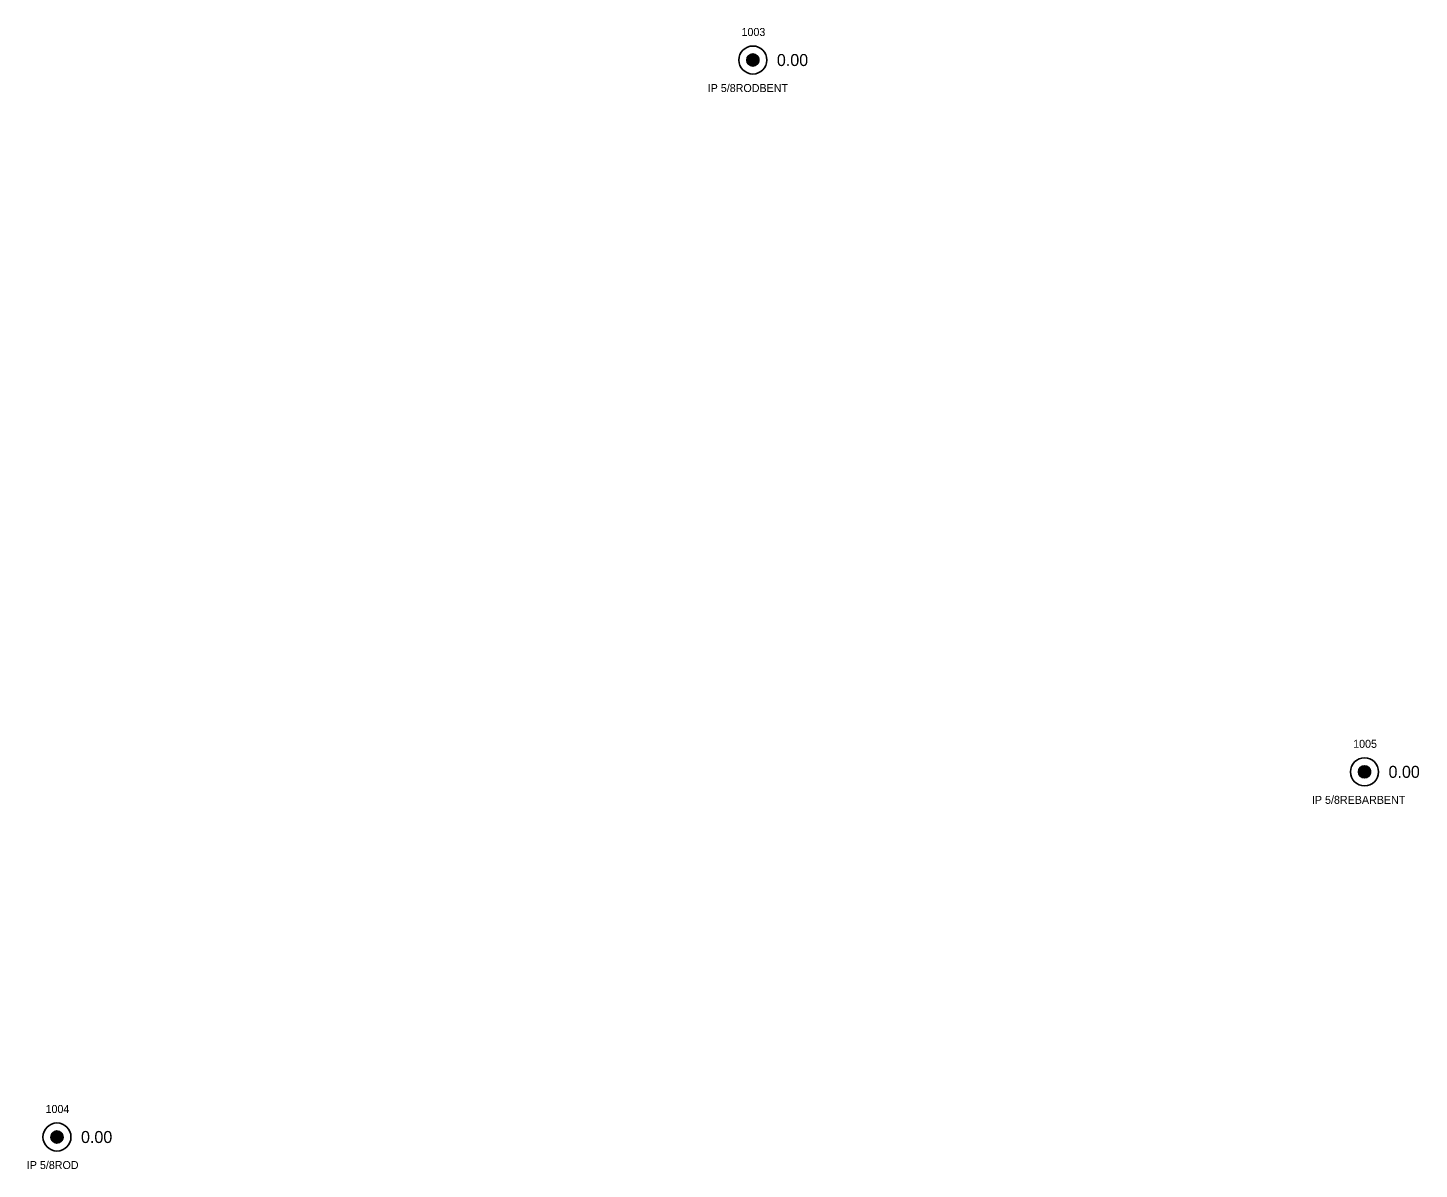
# Model space of a CAD drawing. Extents: x 2139392 to 2143384, y 505395 to 510520.
# Drawn here: x 2140586.9 to 2140760.7, y 505394.8 to 505537.4 of the extents above; entities that cross this region are included whole.
import ezdxf

# ---------------------------------------------------------------- set-up
doc = ezdxf.new("R2010")
doc.units = 0
for name, color, linetype in [('RD_EX_DV_Prop_txCode', 7, 'Continuous'), ('RD_EX_DV_PropPin', 7, 'Continuous'), ('RD_EX_TX_DV_Prop_ELEV', 7, 'Continuous'), ('RD_SMD_Locator', 7, 'Continuous')]:
    doc.layers.add(name, color=color, linetype=linetype)

msp = doc.modelspace()

# ---------------------------------------------------------------- linework, layer by layer
at = {"layer": 'RD_EX_DV_PropPin'}
for p, q in [((2140676.75, 505533.18), (2140676.75, 505533.57)), ((2140676.78, 505533.08), (2140676.78, 505533.67)), ((2140676.82, 505533.01), (2140676.82, 505533.74)), ((2140676.85, 505532.95), (2140676.85, 505533.8)), ((2140676.89, 505532.9), (2140676.89, 505533.85)), ((2140676.92, 505532.86), (2140676.92, 505533.89)), ((2140676.96, 505532.82), (2140676.96, 505533.93)), ((2140676.99, 505532.79), (2140676.99, 505533.96)), ((2140677.03, 505532.76), (2140677.03, 505533.98)), ((2140677.06, 505532.74), (2140677.06, 505534.01)), ((2140677.1, 505532.72), (2140677.1, 505534.03)), ((2140677.13, 505532.7), (2140677.13, 505534.05)), ((2140677.17, 505532.68), (2140677.17, 505534.07)), ((2140677.2, 505532.67), (2140677.2, 505534.08)), ((2140677.24, 505532.65), (2140677.24, 505534.1)), ((2140677.27, 505532.64), (2140677.27, 505534.11)), ((2140677.31, 505532.63), (2140677.31, 505534.12)), ((2140677.34, 505532.63), (2140677.34, 505534.12)), ((2140677.38, 505532.62), (2140677.38, 505534.13)), ((2140677.41, 505532.62), (2140677.41, 505534.13)), ((2140677.45, 505532.61), (2140677.45, 505534.14)), ((2140677.48, 505532.61), (2140677.48, 505534.14)), ((2140677.52, 505532.61), (2140677.52, 505534.14)), ((2140677.55, 505532.62), (2140677.55, 505534.13)), ((2140677.59, 505532.62), (2140677.59, 505534.13)), ((2140677.62, 505532.63), (2140677.62, 505534.12)), ((2140677.66, 505532.63), (2140677.66, 505534.12)), ((2140677.69, 505532.64), (2140677.69, 505534.11)), ((2140677.73, 505532.65), (2140677.73, 505534.1)), ((2140677.76, 505532.67), (2140677.76, 505534.08)), ((2140677.8, 505532.68), (2140677.8, 505534.07)), ((2140677.83, 505532.7), (2140677.83, 505534.05)), ((2140677.87, 505532.72), (2140677.87, 505534.03)), ((2140677.9, 505532.74), (2140677.9, 505534.01)), ((2140677.94, 505532.76), (2140677.94, 505533.98)), ((2140677.97, 505532.79), (2140677.97, 505533.96)), ((2140678.01, 505532.82), (2140678.01, 505533.93)), ((2140678.04, 505532.86), (2140678.04, 505533.89)), ((2140678.08, 505532.9), (2140678.08, 505533.85)), ((2140678.11, 505532.95), (2140678.11, 505533.8)), ((2140678.15, 505533.01), (2140678.15, 505533.74)), ((2140678.18, 505533.08), (2140678.18, 505533.67)), ((2140678.22, 505533.18), (2140678.22, 505533.57)), ((2140753.16, 505444.27), (2140753.16, 505444.66)), ((2140753.19, 505444.16), (2140753.19, 505444.76)), ((2140753.23, 505444.09), (2140753.23, 505444.83)), ((2140753.26, 505444.04), (2140753.26, 505444.89)), ((2140753.3, 505443.99), (2140753.3, 505444.94)), ((2140753.33, 505443.95), (2140753.33, 505444.98)), ((2140753.37, 505443.91), (2140753.37, 505445.01)), ((2140753.4, 505443.88), (2140753.4, 505445.04)), ((2140753.44, 505443.85), (2140753.44, 505445.07)), ((2140753.47, 505443.83), (2140753.47, 505445.1)), ((2140753.51, 505443.81), (2140753.51, 505445.12)), ((2140753.54, 505443.79), (2140753.54, 505445.14)), ((2140753.58, 505443.77), (2140753.58, 505445.15)), ((2140753.61, 505443.75), (2140753.61, 505445.17)), ((2140753.65, 505443.74), (2140753.65, 505445.18)), ((2140753.68, 505443.73), (2140753.68, 505445.19)), ((2140753.72, 505443.72), (2140753.72, 505445.2)), ((2140753.75, 505443.71), (2140753.75, 505445.21)), ((2140753.79, 505443.71), (2140753.79, 505445.22)), ((2140753.82, 505443.7), (2140753.82, 505445.22)), ((2140753.86, 505443.7), (2140753.86, 505445.22)), ((2140753.89, 505443.7), (2140753.89, 505445.22)), ((2140753.93, 505443.7), (2140753.93, 505445.22)), ((2140753.96, 505443.7), (2140753.96, 505445.22)), ((2140754, 505443.71), (2140754, 505445.22)), ((2140754.03, 505443.71), (2140754.03, 505445.21)), ((2140754.07, 505443.72), (2140754.07, 505445.2)), ((2140754.1, 505443.73), (2140754.1, 505445.19)), ((2140754.14, 505443.74), (2140754.14, 505445.18)), ((2140754.17, 505443.75), (2140754.17, 505445.17)), ((2140754.21, 505443.77), (2140754.21, 505445.15)), ((2140754.24, 505443.79), (2140754.24, 505445.14)), ((2140754.28, 505443.81), (2140754.28, 505445.12)), ((2140754.31, 505443.83), (2140754.31, 505445.1)), ((2140754.35, 505443.85), (2140754.35, 505445.07)), ((2140754.38, 505443.88), (2140754.38, 505445.04)), ((2140754.42, 505443.91), (2140754.42, 505445.01)), ((2140754.45, 505443.95), (2140754.45, 505444.98)), ((2140754.49, 505443.99), (2140754.49, 505444.94)), ((2140754.52, 505444.04), (2140754.52, 505444.89)), ((2140754.56, 505444.09), (2140754.56, 505444.83)), ((2140754.59, 505444.16), (2140754.59, 505444.76)), ((2140754.63, 505444.27), (2140754.63, 505444.66)), ((2140589.88, 505398.48), (2140589.88, 505399.22)), ((2140589.92, 505398.42), (2140589.92, 505399.27)), ((2140589.95, 505398.37), (2140589.95, 505399.32)), ((2140589.99, 505398.33), (2140589.99, 505399.36)), ((2140590.02, 505398.3), (2140590.02, 505399.4)), ((2140590.06, 505398.27), (2140590.06, 505399.43)), ((2140590.09, 505398.24), (2140590.09, 505399.46)), ((2140590.13, 505398.21), (2140590.13, 505399.48)), ((2140590.16, 505398.19), (2140590.16, 505399.5)), ((2140590.2, 505398.17), (2140590.2, 505399.52)), ((2140590.23, 505398.15), (2140590.23, 505399.54)), ((2140590.27, 505398.14), (2140590.27, 505399.55)), ((2140590.3, 505398.13), (2140590.3, 505399.57)), ((2140590.34, 505398.12), (2140590.34, 505399.58)), ((2140590.37, 505398.11), (2140590.37, 505399.59)), ((2140590.41, 505398.1), (2140590.41, 505399.6)), ((2140590.44, 505398.09), (2140590.44, 505399.6)), ((2140590.48, 505398.09), (2140590.48, 505399.6)), ((2140590.51, 505398.09), (2140590.51, 505399.61)), ((2140590.55, 505398.09), (2140590.55, 505399.61)), ((2140590.58, 505398.09), (2140590.58, 505399.61)), ((2140590.62, 505398.09), (2140590.62, 505399.6)), ((2140590.65, 505398.09), (2140590.65, 505399.6)), ((2140590.69, 505398.1), (2140590.69, 505399.6)), ((2140590.72, 505398.11), (2140590.72, 505399.59)), ((2140590.76, 505398.12), (2140590.76, 505399.58)), ((2140590.79, 505398.13), (2140590.79, 505399.57)), ((2140590.83, 505398.14), (2140590.83, 505399.55)), ((2140590.86, 505398.15), (2140590.86, 505399.54)), ((2140590.9, 505398.17), (2140590.9, 505399.52)), ((2140590.93, 505398.19), (2140590.93, 505399.5)), ((2140590.97, 505398.21), (2140590.97, 505399.48)), ((2140591, 505398.24), (2140591, 505399.46)), ((2140591.04, 505398.27), (2140591.04, 505399.43)), ((2140591.07, 505398.3), (2140591.07, 505399.4)), ((2140591.11, 505398.33), (2140591.11, 505399.36)), ((2140591.14, 505398.37), (2140591.14, 505399.32)), ((2140591.18, 505398.42), (2140591.18, 505399.27)), ((2140591.21, 505398.48), (2140591.21, 505399.22)), ((2140589.81, 505398.65), (2140589.81, 505399.04)), ((2140589.85, 505398.55), (2140589.85, 505399.15)), ((2140591.25, 505398.55), (2140591.25, 505399.15)), ((2140591.28, 505398.65), (2140591.28, 505399.04))]:
    msp.add_line(p, q, dxfattribs=at)
for centre, radius in [((2140677.48, 505533.37), 1.75), ((2140677.48, 505533.37), 0.761), ((2140753.89, 505444.46), 1.75), ((2140753.89, 505444.46), 0.761), ((2140590.55, 505398.85), 1.75), ((2140590.55, 505398.85), 0.761)]:
    msp.add_circle(centre, radius, dxfattribs=at)
at = {"layer": 'RD_SMD_Locator'}
for centre in [(2140677.48, 505533.37), (2140753.89, 505444.46), (2140590.55, 505398.85)]:
    msp.add_circle(centre, 0.15, dxfattribs=at)

# ---------------------------------------------------------------- texts
at = {"layer": 'RD_EX_DV_Prop_txCode'}
for s, p in [('1003', (2140676.06, 505536.37)), ('IP 5/8RODBENT', (2140671.84, 505529.37)), ('1005', (2140752.47, 505447.46)), ('IP 5/8REBARBENT', (2140747.32, 505440.46)), ('1004', (2140589.12, 505401.85)), ('IP 5/8ROD', (2140586.78, 505394.85))]:
    msp.add_text(s, height=1, dxfattribs=at).set_placement(p)
at = {"layer": 'RD_EX_TX_DV_Prop_ELEV'}
for p in [(2140680.48, 505532.62), (2140756.89, 505443.71), (2140593.55, 505398.1)]:
    msp.add_text('0.00', height=1.5, dxfattribs=at).set_placement(p)

doc.saveas('drawing.dxf')
